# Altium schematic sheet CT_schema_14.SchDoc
size 389 x 385 mm
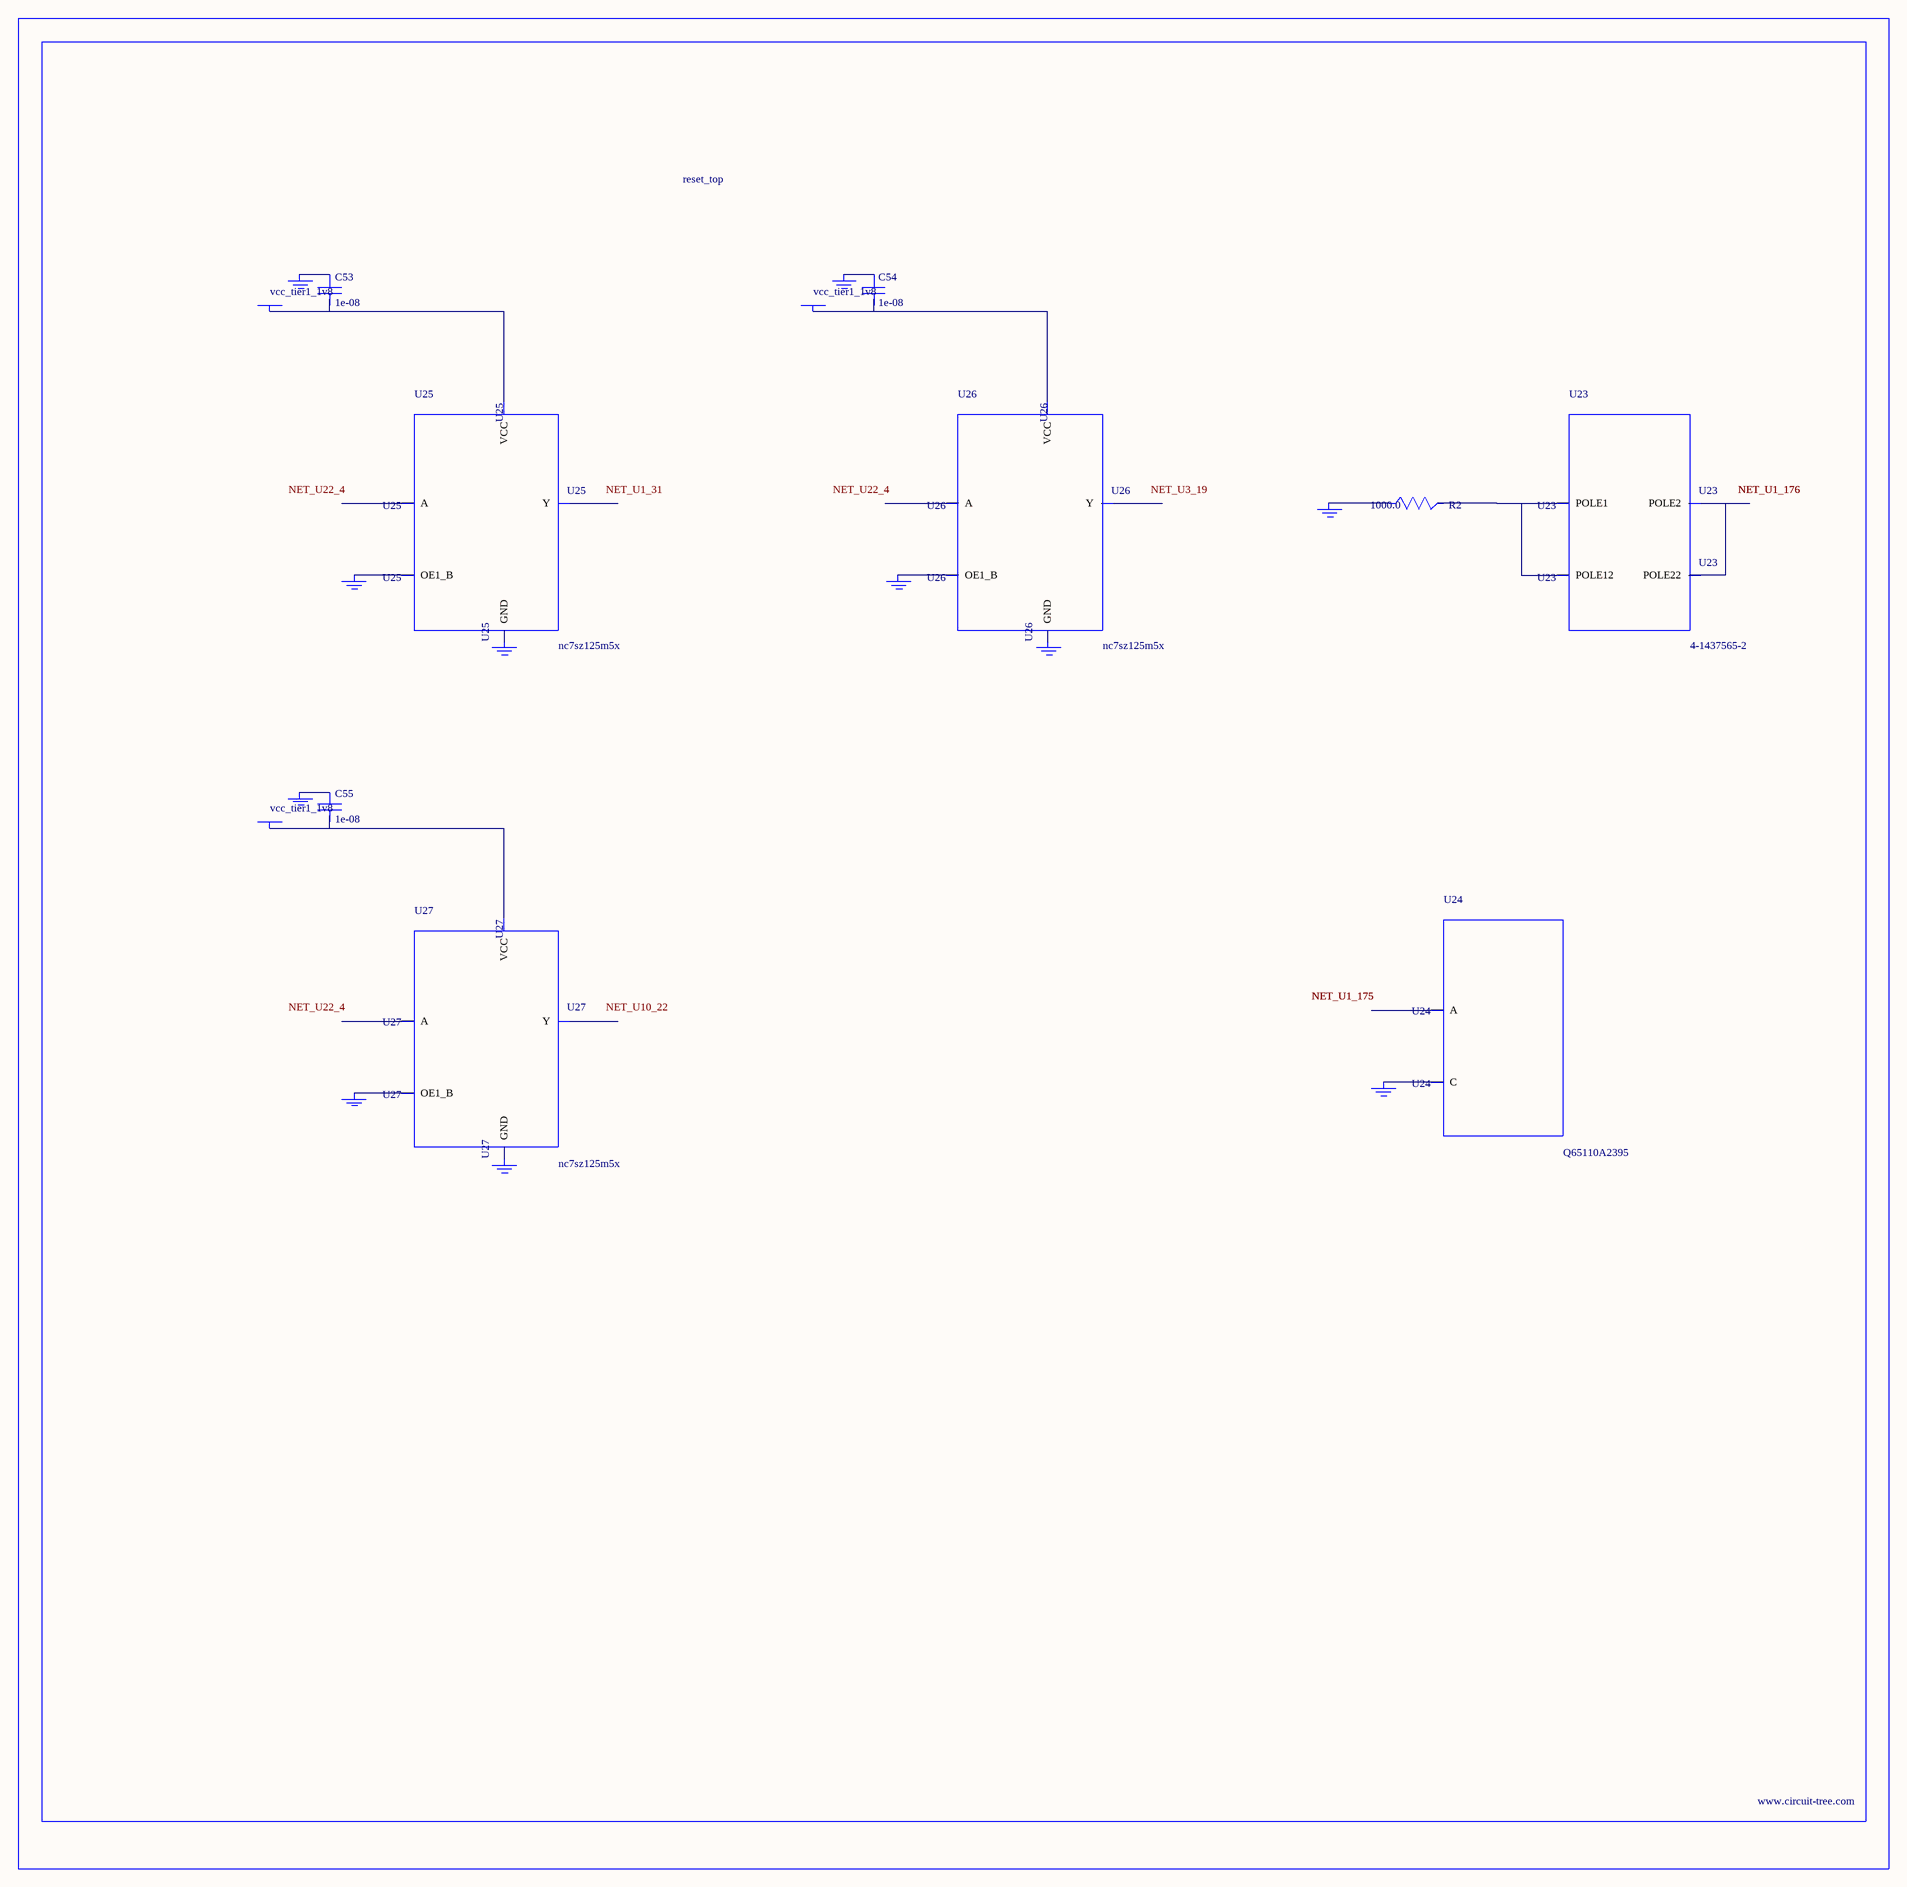
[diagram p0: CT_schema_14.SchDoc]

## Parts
BORDER13  (no value)
C53  1e-08  [C0402]
C54  1e-08  [C0402]
C55  1e-08  [C0402]
GND_INSTANCE_13_0  (no value)
GND_INSTANCE_13_1  (no value)
GND_INSTANCE_13_2  (no value)
GND_INSTANCE_13_3  (no value)
GND_INSTANCE_13_4  (no value)
GND_INSTANCE_13_5  (no value)
GND_INSTANCE_13_6  (no value)
GND_INSTANCE_13_7  (no value)
GND_INSTANCE_13_8  (no value)
GND_INSTANCE_13_9  (no value)
GND_INSTANCE_13_10  (no value)
POWER_INSTANCE_13_0  vcc_tier1_1v8
POWER_INSTANCE_13_1  vcc_tier1_1v8
POWER_INSTANCE_13_2  vcc_tier1_1v8
R2  1000.0  [R0603]
U23  4-1437565-2  [SW_4-1437565-2]
U24  Q65110A2395  [LGM67K-G1J2-24-Z]
U25  nc7sz125m5x  [NC7SZ125M5X]
U26  nc7sz125m5x  [NC7SZ125M5X]
U27  nc7sz125m5x  [NC7SZ125M5X]

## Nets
NetC53_1: C53.1 GND_INSTANCE_13_2.0(GND)
NetC53_2: C53.2 POWER_INSTANCE_13_0.0(PWR) U25.5(VCC)
NetC54_1: C54.1 GND_INSTANCE_13_5.0(GND)
NetC54_2: C54.2 POWER_INSTANCE_13_1.0(PWR) U26.5(VCC)
NetC55_1: C55.1 GND_INSTANCE_13_8.0(GND)
NetC55_2: C55.2 POWER_INSTANCE_13_2.0(PWR) U27.5(VCC)
NetGND_INSTANCE_13_0_0: GND_INSTANCE_13_0.0(GND) R2.1
NetGND_INSTANCE_13_1_0: GND_INSTANCE_13_1.0(GND) U24.C
NetGND_INSTANCE_13_3_0: GND_INSTANCE_13_3.0(GND) U25.1(OE1_B)
NetGND_INSTANCE_13_4_0: GND_INSTANCE_13_4.0(GND) U25.3(GND)
NetGND_INSTANCE_13_6_0: GND_INSTANCE_13_6.0(GND) U26.1(OE1_B)
NetGND_INSTANCE_13_7_0: GND_INSTANCE_13_7.0(GND) U26.3(GND)
NetGND_INSTANCE_13_9_0: GND_INSTANCE_13_9.0(GND) U27.1(OE1_B)
NetGND_INSTANCE_13_10_0: GND_INSTANCE_13_10.0(GND) U27.3(GND)
NetR2_2: R2.2 U23.1(POLE1) U23.2(POLE12)
NetU23_3: U23.3(POLE2) U23.4(POLE22)

Not connected (* = marked no-connect by the designer): U24 A; U25 2(A) 4(Y); U26 2(A) 4(Y); U27 2(A) 4(Y)

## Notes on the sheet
- Labels drawn without touching a wire or pin: NET_U1_31, NET_U3_19, NET_U10_22, NET_U22_4

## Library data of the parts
BORDER13 = BORDER_PAGE13
C53-C55 = C0402C103K3RAC
GND_INSTANCE_13_0-GND_INSTANCE_13_10 = GND
POWER_INSTANCE_13_0-POWER_INSTANCE_13_2 = PWR
R2 = RC0603JR-071KL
